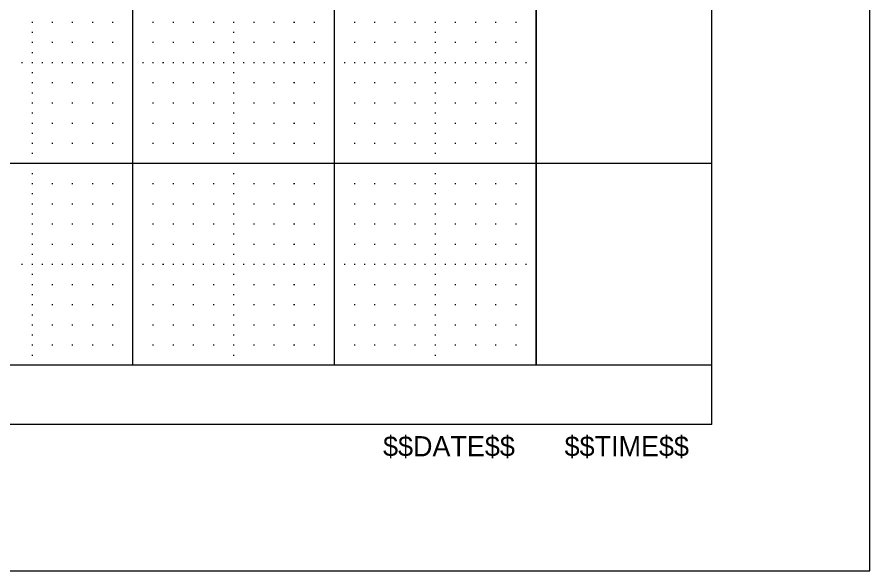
# Model space of a CAD drawing. Extents: x -1.6 to 32.4, y -0.7 to 21.3.
# Drawn here: x 28.17 to 32.402, y -0.727 to 2.018 of the extents above; entities that cross this region are included whole.
import ezdxf

# ---------------------------------------------------------------- set-up
doc = ezdxf.new("R2010")
doc.units = 0
for name, color, linetype in [('Level 1', 7, 'Continuous'), ('Level 4', 7, 'Continuous'), ('Level 48', 7, 'Continuous'), ('Level 5', 7, 'Continuous'), ('Level 63', 7, 'Continuous'), ('R_Border_Dark', 7, 'Continuous')]:
    doc.layers.add(name, color=color, linetype=linetype)

msp = doc.modelspace()

# ---------------------------------------------------------------- linework, layer by layer
at = {"layer": 'Level 1'}
for q in [(31.617, 20.545), (-0.001, -0.001)]:
    msp.add_line((31.617, -0.001), q, dxfattribs=at)
at = {"layer": 'Level 4'}
msp.add_line((31.617, 0.293), (-0.001, 0.293), dxfattribs=at)
at = {"layer": 'Level 5'}
for p, q in [((28.2425, 1.993), (28.2475, 1.993)), ((28.3425, 1.993), (28.3475, 1.993)), ((28.4425, 1.993), (28.4475, 1.993)), ((28.5425, 1.993), (28.5475, 1.993)), ((28.6425, 1.993), (28.6475, 1.993)), ((28.8425, 1.993), (28.8475, 1.993)), ((28.9425, 1.993), (28.9475, 1.993)), ((29.0425, 1.993), (29.0475, 1.993)), ((29.1425, 1.993), (29.1475, 1.993)), ((29.2425, 1.993), (29.2475, 1.993)), ((29.3425, 1.993), (29.3475, 1.993)), ((29.4425, 1.993), (29.4475, 1.993)), ((29.5425, 1.993), (29.5475, 1.993)), ((29.6425, 1.993), (29.6475, 1.993)), ((29.8425, 1.993), (29.8475, 1.993)), ((29.9425, 1.993), (29.9475, 1.993)), ((30.0425, 1.993), (30.0475, 1.993)), ((30.1425, 1.993), (30.1475, 1.993)), ((30.2425, 1.993), (30.2475, 1.993)), ((30.3425, 1.993), (30.3475, 1.993)), ((30.4425, 1.993), (30.4475, 1.993)), ((30.5425, 1.993), (30.5475, 1.993)), ((30.6425, 1.993), (30.6475, 1.993)), ((28.2425, 1.943), (28.2475, 1.943)), ((29.2425, 1.943), (29.2475, 1.943)), ((30.2425, 1.943), (30.2475, 1.943)), ((28.2425, 1.893), (28.2475, 1.893)), ((28.3425, 1.893), (28.3475, 1.893)), ((28.4425, 1.893), (28.4475, 1.893)), ((28.5425, 1.893), (28.5475, 1.893)), ((28.6425, 1.893), (28.6475, 1.893)), ((28.8425, 1.893), (28.8475, 1.893)), ((28.9425, 1.893), (28.9475, 1.893)), ((29.0425, 1.893), (29.0475, 1.893)), ((29.1425, 1.893), (29.1475, 1.893)), ((29.2425, 1.893), (29.2475, 1.893)), ((29.3425, 1.893), (29.3475, 1.893)), ((29.4425, 1.893), (29.4475, 1.893)), ((29.5425, 1.893), (29.5475, 1.893)), ((29.6425, 1.893), (29.6475, 1.893)), ((29.8425, 1.893), (29.8475, 1.893)), ((29.9425, 1.893), (29.9475, 1.893)), ((30.0425, 1.893), (30.0475, 1.893)), ((30.1425, 1.893), (30.1475, 1.893)), ((30.2425, 1.893), (30.2475, 1.893)), ((30.3425, 1.893), (30.3475, 1.893)), ((30.4425, 1.893), (30.4475, 1.893)), ((30.5425, 1.893), (30.5475, 1.893)), ((30.6425, 1.893), (30.6475, 1.893)), ((28.2425, 1.843), (28.2475, 1.843)), ((29.2425, 1.843), (29.2475, 1.843)), ((30.2425, 1.843), (30.2475, 1.843)), ((28.1925, 1.793), (28.1975, 1.793)), ((28.2425, 1.793), (28.2475, 1.793)), ((28.2925, 1.793), (28.2975, 1.793)), ((28.3425, 1.793), (28.3475, 1.793)), ((28.3925, 1.793), (28.3975, 1.793)), ((28.4425, 1.793), (28.4475, 1.793)), ((28.4925, 1.793), (28.4975, 1.793)), ((28.5425, 1.793), (28.5475, 1.793)), ((28.5925, 1.793), (28.5975, 1.793)), ((28.6425, 1.793), (28.6475, 1.793)), ((28.6925, 1.793), (28.6975, 1.793)), ((28.7925, 1.793), (28.7975, 1.793)), ((28.8425, 1.793), (28.8475, 1.793)), ((28.8925, 1.793), (28.8975, 1.793)), ((28.9425, 1.793), (28.9475, 1.793)), ((28.9925, 1.793), (28.9975, 1.793)), ((29.0425, 1.793), (29.0475, 1.793)), ((29.0925, 1.793), (29.0975, 1.793)), ((29.1425, 1.793), (29.1475, 1.793)), ((29.1925, 1.793), (29.1975, 1.793)), ((29.2425, 1.793), (29.2475, 1.793)), ((29.2925, 1.793), (29.2975, 1.793)), ((29.3425, 1.793), (29.3475, 1.793)), ((29.3925, 1.793), (29.3975, 1.793)), ((29.4425, 1.793), (29.4475, 1.793)), ((29.4925, 1.793), (29.4975, 1.793)), ((29.5425, 1.793), (29.5475, 1.793)), ((29.5925, 1.793), (29.5975, 1.793)), ((29.6425, 1.793), (29.6475, 1.793)), ((29.6925, 1.793), (29.6975, 1.793)), ((29.7925, 1.793), (29.7975, 1.793)), ((29.8425, 1.793), (29.8475, 1.793)), ((29.8925, 1.793), (29.8975, 1.793)), ((29.9425, 1.793), (29.9475, 1.793)), ((29.9925, 1.793), (29.9975, 1.793)), ((30.0425, 1.793), (30.0475, 1.793)), ((30.0925, 1.793), (30.0975, 1.793)), ((30.1425, 1.793), (30.1475, 1.793)), ((30.1925, 1.793), (30.1975, 1.793)), ((30.2425, 1.793), (30.2475, 1.793)), ((30.2925, 1.793), (30.2975, 1.793)), ((30.3425, 1.793), (30.3475, 1.793)), ((30.3925, 1.793), (30.3975, 1.793)), ((30.4425, 1.793), (30.4475, 1.793)), ((30.4925, 1.793), (30.4975, 1.793)), ((30.5425, 1.793), (30.5475, 1.793)), ((30.5925, 1.793), (30.5975, 1.793)), ((30.6425, 1.793), (30.6475, 1.793)), ((30.6925, 1.793), (30.6975, 1.793)), ((28.2425, 1.743), (28.2475, 1.743)), ((29.2425, 1.743), (29.2475, 1.743)), ((30.2425, 1.743), (30.2475, 1.743)), ((28.2425, 1.693), (28.2475, 1.693)), ((28.3425, 1.693), (28.3475, 1.693)), ((28.4425, 1.693), (28.4475, 1.693)), ((28.5425, 1.693), (28.5475, 1.693)), ((28.6425, 1.693), (28.6475, 1.693)), ((28.8425, 1.693), (28.8475, 1.693)), ((28.9425, 1.693), (28.9475, 1.693)), ((29.0425, 1.693), (29.0475, 1.693)), ((29.1425, 1.693), (29.1475, 1.693)), ((29.2425, 1.693), (29.2475, 1.693)), ((29.3425, 1.693), (29.3475, 1.693)), ((29.4425, 1.693), (29.4475, 1.693)), ((29.5425, 1.693), (29.5475, 1.693)), ((29.6425, 1.693), (29.6475, 1.693)), ((29.8425, 1.693), (29.8475, 1.693)), ((29.9425, 1.693), (29.9475, 1.693)), ((30.0425, 1.693), (30.0475, 1.693)), ((30.1425, 1.693), (30.1475, 1.693)), ((30.2425, 1.693), (30.2475, 1.693)), ((30.3425, 1.693), (30.3475, 1.693)), ((30.4425, 1.693), (30.4475, 1.693)), ((30.5425, 1.693), (30.5475, 1.693)), ((30.6425, 1.693), (30.6475, 1.693)), ((28.2425, 1.643), (28.2475, 1.643)), ((29.2425, 1.643), (29.2475, 1.643)), ((30.2425, 1.643), (30.2475, 1.643)), ((28.2425, 1.593), (28.2475, 1.593)), ((28.3425, 1.593), (28.3475, 1.593)), ((28.4425, 1.593), (28.4475, 1.593)), ((28.5425, 1.593), (28.5475, 1.593)), ((28.6425, 1.593), (28.6475, 1.593)), ((28.8425, 1.593), (28.8475, 1.593)), ((28.9425, 1.593), (28.9475, 1.593)), ((29.0425, 1.593), (29.0475, 1.593)), ((29.1425, 1.593), (29.1475, 1.593)), ((29.2425, 1.593), (29.2475, 1.593)), ((29.3425, 1.593), (29.3475, 1.593)), ((29.4425, 1.593), (29.4475, 1.593)), ((29.5425, 1.593), (29.5475, 1.593)), ((29.6425, 1.593), (29.6475, 1.593)), ((29.8425, 1.593), (29.8475, 1.593)), ((29.9425, 1.593), (29.9475, 1.593)), ((30.0425, 1.593), (30.0475, 1.593)), ((30.1425, 1.593), (30.1475, 1.593)), ((30.2425, 1.593), (30.2475, 1.593)), ((30.3425, 1.593), (30.3475, 1.593)), ((30.4425, 1.593), (30.4475, 1.593)), ((30.5425, 1.593), (30.5475, 1.593)), ((30.6425, 1.593), (30.6475, 1.593)), ((28.2425, 1.543), (28.2475, 1.543)), ((29.2425, 1.543), (29.2475, 1.543)), ((30.2425, 1.543), (30.2475, 1.543)), ((28.2425, 1.493), (28.2475, 1.493)), ((28.3425, 1.493), (28.3475, 1.493)), ((28.4425, 1.493), (28.4475, 1.493)), ((28.5425, 1.493), (28.5475, 1.493)), ((28.6425, 1.493), (28.6475, 1.493)), ((28.8425, 1.493), (28.8475, 1.493)), ((28.9425, 1.493), (28.9475, 1.493)), ((29.0425, 1.493), (29.0475, 1.493)), ((29.1425, 1.493), (29.1475, 1.493)), ((29.2425, 1.493), (29.2475, 1.493)), ((29.3425, 1.493), (29.3475, 1.493)), ((29.4425, 1.493), (29.4475, 1.493)), ((29.5425, 1.493), (29.5475, 1.493)), ((29.6425, 1.493), (29.6475, 1.493)), ((29.8425, 1.493), (29.8475, 1.493)), ((29.9425, 1.493), (29.9475, 1.493)), ((30.0425, 1.493), (30.0475, 1.493)), ((30.1425, 1.493), (30.1475, 1.493)), ((30.2425, 1.493), (30.2475, 1.493)), ((30.3425, 1.493), (30.3475, 1.493)), ((30.4425, 1.493), (30.4475, 1.493)), ((30.5425, 1.493), (30.5475, 1.493)), ((30.6425, 1.493), (30.6475, 1.493)), ((28.2425, 1.443), (28.2475, 1.443)), ((29.2425, 1.443), (29.2475, 1.443)), ((30.2425, 1.443), (30.2475, 1.443)), ((28.2425, 1.393), (28.2475, 1.393)), ((28.3425, 1.393), (28.3475, 1.393)), ((28.4425, 1.393), (28.4475, 1.393)), ((28.5425, 1.393), (28.5475, 1.393)), ((28.6425, 1.393), (28.6475, 1.393)), ((28.8425, 1.393), (28.8475, 1.393)), ((28.9425, 1.393), (28.9475, 1.393)), ((29.0425, 1.393), (29.0475, 1.393)), ((29.1425, 1.393), (29.1475, 1.393)), ((29.2425, 1.393), (29.2475, 1.393)), ((29.3425, 1.393), (29.3475, 1.393)), ((29.4425, 1.393), (29.4475, 1.393)), ((29.5425, 1.393), (29.5475, 1.393)), ((29.6425, 1.393), (29.6475, 1.393)), ((29.8425, 1.393), (29.8475, 1.393)), ((29.9425, 1.393), (29.9475, 1.393)), ((30.0425, 1.393), (30.0475, 1.393)), ((30.1425, 1.393), (30.1475, 1.393)), ((30.2425, 1.393), (30.2475, 1.393)), ((30.3425, 1.393), (30.3475, 1.393)), ((30.4425, 1.393), (30.4475, 1.393)), ((30.5425, 1.393), (30.5475, 1.393)), ((30.6425, 1.393), (30.6475, 1.393)), ((28.2425, 1.343), (28.2475, 1.343)), ((29.2425, 1.343), (29.2475, 1.343)), ((30.2425, 1.343), (30.2475, 1.343)), ((28.2425, 1.243), (28.2475, 1.243)), ((29.2425, 1.243), (29.2475, 1.243)), ((30.2425, 1.243), (30.2475, 1.243)), ((28.2425, 1.193), (28.2475, 1.193)), ((28.3425, 1.193), (28.3475, 1.193)), ((28.4425, 1.193), (28.4475, 1.193)), ((28.5425, 1.193), (28.5475, 1.193)), ((28.6425, 1.193), (28.6475, 1.193)), ((28.8425, 1.193), (28.8475, 1.193)), ((28.9425, 1.193), (28.9475, 1.193)), ((29.0425, 1.193), (29.0475, 1.193)), ((29.1425, 1.193), (29.1475, 1.193)), ((29.2425, 1.193), (29.2475, 1.193)), ((29.3425, 1.193), (29.3475, 1.193)), ((29.4425, 1.193), (29.4475, 1.193)), ((29.5425, 1.193), (29.5475, 1.193)), ((29.6425, 1.193), (29.6475, 1.193)), ((29.8425, 1.193), (29.8475, 1.193)), ((29.9425, 1.193), (29.9475, 1.193)), ((30.0425, 1.193), (30.0475, 1.193)), ((30.1425, 1.193), (30.1475, 1.193)), ((30.2425, 1.193), (30.2475, 1.193)), ((30.3425, 1.193), (30.3475, 1.193)), ((30.4425, 1.193), (30.4475, 1.193)), ((30.5425, 1.193), (30.5475, 1.193)), ((30.6425, 1.193), (30.6475, 1.193)), ((28.2425, 1.143), (28.2475, 1.143)), ((29.2425, 1.143), (29.2475, 1.143)), ((30.2425, 1.143), (30.2475, 1.143)), ((28.2425, 1.093), (28.2475, 1.093)), ((28.3425, 1.093), (28.3475, 1.093)), ((28.4425, 1.093), (28.4475, 1.093)), ((28.5425, 1.093), (28.5475, 1.093)), ((28.6425, 1.093), (28.6475, 1.093)), ((28.8425, 1.093), (28.8475, 1.093)), ((28.9425, 1.093), (28.9475, 1.093)), ((29.0425, 1.093), (29.0475, 1.093)), ((29.1425, 1.093), (29.1475, 1.093)), ((29.2425, 1.093), (29.2475, 1.093)), ((29.3425, 1.093), (29.3475, 1.093)), ((29.4425, 1.093), (29.4475, 1.093)), ((29.5425, 1.093), (29.5475, 1.093)), ((29.6425, 1.093), (29.6475, 1.093)), ((29.8425, 1.093), (29.8475, 1.093)), ((29.9425, 1.093), (29.9475, 1.093)), ((30.0425, 1.093), (30.0475, 1.093)), ((30.1425, 1.093), (30.1475, 1.093)), ((30.2425, 1.093), (30.2475, 1.093)), ((30.3425, 1.093), (30.3475, 1.093)), ((30.4425, 1.093), (30.4475, 1.093)), ((30.5425, 1.093), (30.5475, 1.093)), ((30.6425, 1.093), (30.6475, 1.093)), ((28.2425, 1.043), (28.2475, 1.043)), ((29.2425, 1.043), (29.2475, 1.043)), ((30.2425, 1.043), (30.2475, 1.043)), ((28.2425, 0.993), (28.2475, 0.993)), ((28.3425, 0.993), (28.3475, 0.993)), ((28.4425, 0.993), (28.4475, 0.993)), ((28.5425, 0.993), (28.5475, 0.993)), ((28.6425, 0.993), (28.6475, 0.993)), ((28.8425, 0.993), (28.8475, 0.993)), ((28.9425, 0.993), (28.9475, 0.993)), ((29.0425, 0.993), (29.0475, 0.993)), ((29.1425, 0.993), (29.1475, 0.993)), ((29.2425, 0.993), (29.2475, 0.993)), ((29.3425, 0.993), (29.3475, 0.993)), ((29.4425, 0.993), (29.4475, 0.993)), ((29.5425, 0.993), (29.5475, 0.993)), ((29.6425, 0.993), (29.6475, 0.993)), ((29.8425, 0.993), (29.8475, 0.993)), ((29.9425, 0.993), (29.9475, 0.993)), ((30.0425, 0.993), (30.0475, 0.993)), ((30.1425, 0.993), (30.1475, 0.993)), ((30.2425, 0.993), (30.2475, 0.993)), ((30.3425, 0.993), (30.3475, 0.993)), ((30.4425, 0.993), (30.4475, 0.993)), ((30.5425, 0.993), (30.5475, 0.993)), ((30.6425, 0.993), (30.6475, 0.993)), ((28.2425, 0.943), (28.2475, 0.943)), ((29.2425, 0.943), (29.2475, 0.943)), ((30.2425, 0.943), (30.2475, 0.943)), ((28.2425, 0.893), (28.2475, 0.893)), ((28.3425, 0.893), (28.3475, 0.893)), ((28.4425, 0.893), (28.4475, 0.893)), ((28.5425, 0.893), (28.5475, 0.893)), ((28.6425, 0.893), (28.6475, 0.893)), ((28.8425, 0.893), (28.8475, 0.893)), ((28.9425, 0.893), (28.9475, 0.893)), ((29.0425, 0.893), (29.0475, 0.893)), ((29.1425, 0.893), (29.1475, 0.893)), ((29.2425, 0.893), (29.2475, 0.893)), ((29.3425, 0.893), (29.3475, 0.893)), ((29.4425, 0.893), (29.4475, 0.893)), ((29.5425, 0.893), (29.5475, 0.893)), ((29.6425, 0.893), (29.6475, 0.893)), ((29.8425, 0.893), (29.8475, 0.893)), ((29.9425, 0.893), (29.9475, 0.893)), ((30.0425, 0.893), (30.0475, 0.893)), ((30.1425, 0.893), (30.1475, 0.893)), ((30.2425, 0.893), (30.2475, 0.893)), ((30.3425, 0.893), (30.3475, 0.893)), ((30.4425, 0.893), (30.4475, 0.893)), ((30.5425, 0.893), (30.5475, 0.893)), ((30.6425, 0.893), (30.6475, 0.893)), ((28.2425, 0.843), (28.2475, 0.843)), ((29.2425, 0.843), (29.2475, 0.843)), ((30.2425, 0.843), (30.2475, 0.843)), ((28.1925, 0.793), (28.1975, 0.793)), ((28.2425, 0.793), (28.2475, 0.793)), ((28.2925, 0.793), (28.2975, 0.793)), ((28.3425, 0.793), (28.3475, 0.793)), ((28.3925, 0.793), (28.3975, 0.793)), ((28.4425, 0.793), (28.4475, 0.793)), ((28.4925, 0.793), (28.4975, 0.793)), ((28.5425, 0.793), (28.5475, 0.793)), ((28.5925, 0.793), (28.5975, 0.793)), ((28.6425, 0.793), (28.6475, 0.793)), ((28.6925, 0.793), (28.6975, 0.793)), ((28.7925, 0.793), (28.7975, 0.793)), ((28.8425, 0.793), (28.8475, 0.793)), ((28.8925, 0.793), (28.8975, 0.793)), ((28.9425, 0.793), (28.9475, 0.793)), ((28.9925, 0.793), (28.9975, 0.793)), ((29.0425, 0.793), (29.0475, 0.793)), ((29.0925, 0.793), (29.0975, 0.793)), ((29.1425, 0.793), (29.1475, 0.793)), ((29.1925, 0.793), (29.1975, 0.793)), ((29.2425, 0.793), (29.2475, 0.793)), ((29.2925, 0.793), (29.2975, 0.793)), ((29.3425, 0.793), (29.3475, 0.793)), ((29.3925, 0.793), (29.3975, 0.793)), ((29.4425, 0.793), (29.4475, 0.793)), ((29.4925, 0.793), (29.4975, 0.793)), ((29.5425, 0.793), (29.5475, 0.793)), ((29.5925, 0.793), (29.5975, 0.793)), ((29.6425, 0.793), (29.6475, 0.793)), ((29.6925, 0.793), (29.6975, 0.793)), ((29.7925, 0.793), (29.7975, 0.793)), ((29.8425, 0.793), (29.8475, 0.793)), ((29.8925, 0.793), (29.8975, 0.793)), ((29.9425, 0.793), (29.9475, 0.793)), ((29.9925, 0.793), (29.9975, 0.793)), ((30.0425, 0.793), (30.0475, 0.793)), ((30.0925, 0.793), (30.0975, 0.793)), ((30.1425, 0.793), (30.1475, 0.793)), ((30.1925, 0.793), (30.1975, 0.793)), ((30.2425, 0.793), (30.2475, 0.793)), ((30.2925, 0.793), (30.2975, 0.793)), ((30.3425, 0.793), (30.3475, 0.793)), ((30.3925, 0.793), (30.3975, 0.793)), ((30.4425, 0.793), (30.4475, 0.793)), ((30.4925, 0.793), (30.4975, 0.793)), ((30.5425, 0.793), (30.5475, 0.793)), ((30.5925, 0.793), (30.5975, 0.793)), ((30.6425, 0.793), (30.6475, 0.793)), ((30.6925, 0.793), (30.6975, 0.793)), ((28.2425, 0.743), (28.2475, 0.743)), ((29.2425, 0.743), (29.2475, 0.743)), ((30.2425, 0.743), (30.2475, 0.743)), ((28.2425, 0.693), (28.2475, 0.693)), ((28.3425, 0.693), (28.3475, 0.693)), ((28.4425, 0.693), (28.4475, 0.693)), ((28.5425, 0.693), (28.5475, 0.693)), ((28.6425, 0.693), (28.6475, 0.693)), ((28.8425, 0.693), (28.8475, 0.693)), ((28.9425, 0.693), (28.9475, 0.693)), ((29.0425, 0.693), (29.0475, 0.693)), ((29.1425, 0.693), (29.1475, 0.693)), ((29.2425, 0.693), (29.2475, 0.693)), ((29.3425, 0.693), (29.3475, 0.693)), ((29.4425, 0.693), (29.4475, 0.693)), ((29.5425, 0.693), (29.5475, 0.693)), ((29.6425, 0.693), (29.6475, 0.693)), ((29.8425, 0.693), (29.8475, 0.693)), ((29.9425, 0.693), (29.9475, 0.693)), ((30.0425, 0.693), (30.0475, 0.693)), ((30.1425, 0.693), (30.1475, 0.693)), ((30.2425, 0.693), (30.2475, 0.693)), ((30.3425, 0.693), (30.3475, 0.693)), ((30.4425, 0.693), (30.4475, 0.693)), ((30.5425, 0.693), (30.5475, 0.693)), ((30.6425, 0.693), (30.6475, 0.693)), ((28.2425, 0.643), (28.2475, 0.643)), ((29.2425, 0.643), (29.2475, 0.643)), ((30.2425, 0.643), (30.2475, 0.643)), ((28.2425, 0.593), (28.2475, 0.593)), ((28.3425, 0.593), (28.3475, 0.593)), ((28.4425, 0.593), (28.4475, 0.593)), ((28.5425, 0.593), (28.5475, 0.593)), ((28.6425, 0.593), (28.6475, 0.593)), ((28.8425, 0.593), (28.8475, 0.593)), ((28.9425, 0.593), (28.9475, 0.593)), ((29.0425, 0.593), (29.0475, 0.593)), ((29.1425, 0.593), (29.1475, 0.593)), ((29.2425, 0.593), (29.2475, 0.593)), ((29.3425, 0.593), (29.3475, 0.593)), ((29.4425, 0.593), (29.4475, 0.593)), ((29.5425, 0.593), (29.5475, 0.593)), ((29.6425, 0.593), (29.6475, 0.593)), ((29.8425, 0.593), (29.8475, 0.593)), ((29.9425, 0.593), (29.9475, 0.593)), ((30.0425, 0.593), (30.0475, 0.593)), ((30.1425, 0.593), (30.1475, 0.593)), ((30.2425, 0.593), (30.2475, 0.593)), ((30.3425, 0.593), (30.3475, 0.593)), ((30.4425, 0.593), (30.4475, 0.593)), ((30.5425, 0.593), (30.5475, 0.593)), ((30.6425, 0.593), (30.6475, 0.593)), ((28.2425, 0.543), (28.2475, 0.543)), ((29.2425, 0.543), (29.2475, 0.543)), ((30.2425, 0.543), (30.2475, 0.543)), ((28.2425, 0.493), (28.2475, 0.493)), ((28.3425, 0.493), (28.3475, 0.493)), ((28.4425, 0.493), (28.4475, 0.493)), ((28.5425, 0.493), (28.5475, 0.493)), ((28.6425, 0.493), (28.6475, 0.493)), ((28.8425, 0.493), (28.8475, 0.493)), ((28.9425, 0.493), (28.9475, 0.493)), ((29.0425, 0.493), (29.0475, 0.493)), ((29.1425, 0.493), (29.1475, 0.493)), ((29.2425, 0.493), (29.2475, 0.493)), ((29.3425, 0.493), (29.3475, 0.493)), ((29.4425, 0.493), (29.4475, 0.493)), ((29.5425, 0.493), (29.5475, 0.493)), ((29.6425, 0.493), (29.6475, 0.493)), ((29.8425, 0.493), (29.8475, 0.493)), ((29.9425, 0.493), (29.9475, 0.493)), ((30.0425, 0.493), (30.0475, 0.493)), ((30.1425, 0.493), (30.1475, 0.493)), ((30.2425, 0.493), (30.2475, 0.493)), ((30.3425, 0.493), (30.3475, 0.493)), ((30.4425, 0.493), (30.4475, 0.493)), ((30.5425, 0.493), (30.5475, 0.493)), ((30.6425, 0.493), (30.6475, 0.493)), ((28.2425, 0.443), (28.2475, 0.443)), ((29.2425, 0.443), (29.2475, 0.443)), ((30.2425, 0.443), (30.2475, 0.443)), ((28.2425, 0.393), (28.2475, 0.393)), ((28.3425, 0.393), (28.3475, 0.393)), ((28.4425, 0.393), (28.4475, 0.393)), ((28.5425, 0.393), (28.5475, 0.393)), ((28.6425, 0.393), (28.6475, 0.393)), ((28.8425, 0.393), (28.8475, 0.393)), ((28.9425, 0.393), (28.9475, 0.393)), ((29.0425, 0.393), (29.0475, 0.393)), ((29.1425, 0.393), (29.1475, 0.393)), ((29.2425, 0.393), (29.2475, 0.393)), ((29.3425, 0.393), (29.3475, 0.393)), ((29.4425, 0.393), (29.4475, 0.393)), ((29.5425, 0.393), (29.5475, 0.393)), ((29.6425, 0.393), (29.6475, 0.393)), ((29.8425, 0.393), (29.8475, 0.393)), ((29.9425, 0.393), (29.9475, 0.393)), ((30.0425, 0.393), (30.0475, 0.393)), ((30.1425, 0.393), (30.1475, 0.393)), ((30.2425, 0.393), (30.2475, 0.393)), ((30.3425, 0.393), (30.3475, 0.393)), ((30.4425, 0.393), (30.4475, 0.393)), ((30.5425, 0.393), (30.5475, 0.393)), ((30.6425, 0.393), (30.6475, 0.393)), ((28.2425, 0.343), (28.2475, 0.343)), ((29.2425, 0.343), (29.2475, 0.343)), ((30.2425, 0.343), (30.2475, 0.343))]:
    msp.add_line(p, q, dxfattribs=at)
at = {"layer": 'Level 63'}
msp.add_lwpolyline([(-1.598, -0.727), (32.402, -0.727), (32.402, 21.273), (-1.598, 21.273)], close=True, dxfattribs=at)
msp.add_lwpolyline([(30.745, 8.293), (30.745, 0.293), (0.745, 0.293), (0.745, 8.293)], dxfattribs=at)
at = {"layer": 'R_Border_Dark'}
for p, q in [((28.745, 0.293), (28.745, 8.293)), ((29.745, 0.293), (29.745, 8.293)), ((30.745, 0.293), (30.745, 8.293)), ((31.617, 1.293), (-0.001, 1.293))]:
    msp.add_line(p, q, dxfattribs=at)
msp.add_lwpolyline([(30.745, 8.293), (30.745, 0.293), (0.745, 0.293), (0.745, 8.293)], dxfattribs=at)

# ---------------------------------------------------------------- texts
at = {"layer": 'Level 48'}
for s, p in [('$$DATE$$', (29.986, -0.159)), ('$$TIME$$', (30.887, -0.159))]:
    msp.add_text(s, height=0.1, dxfattribs=at).set_placement(p)

doc.saveas('drawing.dxf')
